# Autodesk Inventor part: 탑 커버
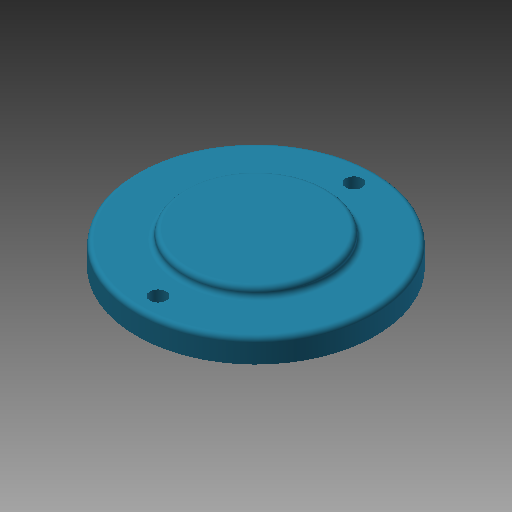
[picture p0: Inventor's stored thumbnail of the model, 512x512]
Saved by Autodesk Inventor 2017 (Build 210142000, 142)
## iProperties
Created: 2017-05
Part Number: 탑 커버
Material: 알루미늄 6061
Document SubType Name: Modeling
Designer: mduedu
Density: 1 g/cm^3
Appearance: 터키옥색
Author: mduedu
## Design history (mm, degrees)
sketch "스케치1"
  geometry: C1 r 25 at (0, 0); 1 further point
  constraints: 1 centre point, 1 coincident
  dimensions: "d31" = 50 diameter of C1
extrude "돌출1" new body sketch "스케치1" distance "d2" = 5; taper "d3" = 0 deg
sketch "스케치2"
  geometry: C1 r 15 at (0, 0); 1 further point
  constraints: 1 centre point, 1 coincident
  dimensions: "d5" = 30 diameter of C1
extrude "돌출2" join sketch "스케치2" distance "d6" = 2; taper "d7" = 0 deg
sketch "스케치3"
  geometry: C1 r 16 at (0, 0); 1 further point
  constraints: 1 centre point, 1 coincident
  dimensions: "d32" = 32 diameter of C1
extrude "돌출3" join sketch "스케치3" distance "d10" = 3; taper "d11" = 0 deg
sketch "스케치4"
  geometry: C1 r 16 at (0, 0) reference; C2 r 14 at (0, 0); 1 further point
  constraints: 1 centre point
  dimensions: "d33" = 2 radial gap between concentric circles of C2 C1
extrude "돌출4" cut sketch "스케치4" distance "d14" = 6; taper "d15" = 0 deg
chamfer "모따기1" distance "d16" = 1; stored, may be unused: second distance "d17" = 2, angle "d18" = 45 deg
fillet "모깎기3" dims "d19" = 1
fillet "모깎기4" dims "d20" = 1
fillet "모깎기5" dims "d21" = 1
sketch "스케치5" dims "d34" = 41
  geometry: C1 r 25 at (0, 0) reference; 2 further points
  constraints: 2 vertical alignment, 1 coincident, 2 other
hole "구멍2" sketch "스케치5" at (0, 20.5) diameter "d35" = 3.4; stored, may be unused: countersink angle "d39" = 90 deg, drill point angle "d41" = 118 deg; dims "d36" = 6, "d37" = 4, "d38" = 2, "d40" = 8
node "솔리드1"
pattern_circular "원형 패턴1" dims angle "d43" = 360 deg
node "투영된 루프2"
